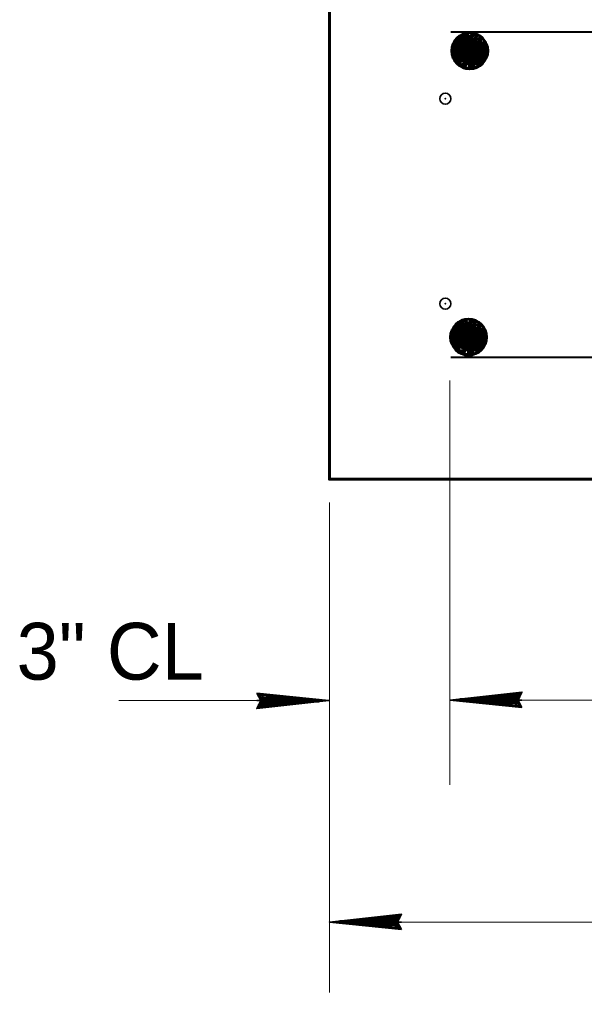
# Model space of a CAD drawing. Extents: x 4.49 to 7.69, y 0.28 to 2.27.
# Drawn here: x 5.7728 to 5.8557, y 1.3387 to 1.4815 of the extents above; entities that cross this region are included whole.
import ezdxf

# ---------------------------------------------------------------- set-up
doc = ezdxf.new("R2010")
doc.units = 0
doc.header["$LTSCALE"] = 0.0033
doc.header["$PDMODE"] = 32
doc.header["$PDSIZE"] = 0.00165
doc.layers.add('1', color=7, linetype='Continuous', lineweight=35)

msp = doc.modelspace()

# ---------------------------------------------------------------- linework, layer by layer
at = {"layer": '1', "lineweight": 40}
for p, q in [((5.836083, 1.479667), (6.217, 1.479667)), ((5.83675, 1.478417), (5.841333, 1.47625)), ((5.837, 1.478), (5.840917, 1.47725)), ((5.837083, 1.478417), (5.841, 1.47775)), ((5.837083, 1.47825), (5.841, 1.4775)), ((5.837167, 1.47875), (5.841, 1.478083)), ((5.839083, 1.477917), (5.840417, 1.478917)), ((5.841167, 1.478083), (5.839917, 1.47925)), ((5.83675, 1.476583), (5.840667, 1.475833)), ((5.836833, 1.477), (5.840667, 1.47625)), ((5.836833, 1.476833), (5.840667, 1.476083)), ((5.836917, 1.477417), (5.84075, 1.47675)), ((5.836917, 1.47725), (5.84075, 1.4765)), ((5.837, 1.477833), (5.840917, 1.477083)), ((5.837, 1.477583), (5.840833, 1.476833)), ((5.836583, 1.475667), (5.840417, 1.474917)), ((5.836583, 1.4755), (5.840417, 1.47475)), ((5.836667, 1.476167), (5.840583, 1.475417)), ((5.836667, 1.476), (5.8405, 1.47525)), ((5.836667, 1.47575), (5.8405, 1.475083)), ((5.840917, 1.47525), (5.837167, 1.474833)), ((5.837, 1.43675), (5.840833, 1.436083)), ((5.838917, 1.435917), (5.84025, 1.436917)), ((5.841, 1.436083), (5.83975, 1.43725)), ((5.836583, 1.436417), (5.841167, 1.43425)), ((5.83675, 1.435417), (5.840583, 1.43475)), ((5.83675, 1.43525), (5.840583, 1.4345)), ((5.836833, 1.436), (5.84075, 1.43525)), ((5.836833, 1.435833), (5.84075, 1.435083)), ((5.836833, 1.435583), (5.840667, 1.434833)), ((5.836917, 1.436417), (5.840833, 1.43575)), ((5.836917, 1.43625), (5.840833, 1.4355)), ((5.836417, 1.433667), (5.84025, 1.432917)), ((5.8365, 1.434167), (5.840417, 1.433417)), ((5.8365, 1.434), (5.840333, 1.43325)), ((5.8365, 1.43375), (5.840333, 1.433083)), ((5.836583, 1.434583), (5.8405, 1.433833)), ((5.836667, 1.435), (5.8405, 1.43425)), ((5.836667, 1.434833), (5.8405, 1.434083)), ((5.836417, 1.4335), (5.84025, 1.43275)), ((5.84075, 1.43325), (5.837, 1.432833)), ((5.836083, 1.431917), (6.216583, 1.431917))]:
    msp.add_line(p, q, dxfattribs=at)
at = {"layer": '1', "lineweight": 60}
for p, q in [((5.837, 1.478417), (5.836833, 1.4755)), ((5.83725, 1.478417), (5.837, 1.4755)), ((5.837417, 1.478417), (5.83725, 1.475417)), ((5.837583, 1.478417), (5.837333, 1.475417)), ((5.83775, 1.478417), (5.837583, 1.475417)), ((5.838, 1.478417), (5.837833, 1.475417)), ((5.83825, 1.478417), (5.838, 1.475417)), ((5.838333, 1.478333), (5.838167, 1.475417)), ((5.8385, 1.478333), (5.838333, 1.475417)), ((5.838667, 1.478333), (5.8385, 1.475417)), ((5.838917, 1.478333), (5.838667, 1.475417)), ((5.839083, 1.478333), (5.838917, 1.475417)), ((5.839333, 1.47825), (5.839083, 1.475333)), ((5.839583, 1.47825), (5.839333, 1.475333)), ((5.83975, 1.47825), (5.839583, 1.475333)), ((5.839833, 1.47825), (5.839667, 1.475333)), ((5.84, 1.47825), (5.839833, 1.475333)), ((5.840083, 1.47825), (5.839917, 1.475333)), ((5.840333, 1.478167), (5.840083, 1.47525)), ((5.8405, 1.478167), (5.840333, 1.47525)), ((5.840667, 1.478167), (5.840417, 1.47525)), ((5.840833, 1.478167), (5.840667, 1.47525)), ((5.841083, 1.478167), (5.840917, 1.47525)), ((5.841333, 1.47625), (5.841167, 1.478083)), ((5.841333, 1.47625), (5.836583, 1.4755)), ((5.836833, 1.436417), (5.836667, 1.4335)), ((5.837083, 1.436417), (5.836833, 1.4335)), ((5.83725, 1.436417), (5.837083, 1.433417)), ((5.837417, 1.436417), (5.837167, 1.433417)), ((5.837583, 1.436417), (5.837417, 1.433417)), ((5.837833, 1.436417), (5.837667, 1.433417)), ((5.838083, 1.436417), (5.837833, 1.433417)), ((5.838167, 1.436333), (5.838, 1.433417)), ((5.838333, 1.436333), (5.838167, 1.433417)), ((5.8385, 1.436333), (5.838333, 1.433417)), ((5.83875, 1.436333), (5.8385, 1.433417)), ((5.838917, 1.436333), (5.83875, 1.433417)), ((5.839167, 1.43625), (5.838917, 1.433333)), ((5.839417, 1.43625), (5.839167, 1.433333)), ((5.839583, 1.43625), (5.839417, 1.433333)), ((5.839667, 1.43625), (5.8395, 1.433333)), ((5.839833, 1.43625), (5.839667, 1.433333)), ((5.839917, 1.43625), (5.83975, 1.433333)), ((5.840167, 1.436167), (5.839917, 1.43325)), ((5.840333, 1.436167), (5.840167, 1.43325)), ((5.8405, 1.436167), (5.84025, 1.43325)), ((5.840667, 1.436167), (5.8405, 1.43325)), ((5.840917, 1.436167), (5.84075, 1.43325)), ((5.841167, 1.43425), (5.841, 1.436083)), ((5.841167, 1.43425), (5.836417, 1.4335))]:
    msp.add_line(p, q, dxfattribs=at)
at = {"layer": '1', "lineweight": 13}
for p, q in [((5.835917, 1.4285), (5.835917, 1.369167)), ((5.81825, 1.410583), (5.81825, 1.338667)), ((5.787333, 1.3815), (5.808167, 1.3815)), ((5.835917, 1.381583), (6.216917, 1.381583)), ((5.81825, 1.349), (6.234583, 1.349))]:
    msp.add_line(p, q, dxfattribs=at)
at = {"layer": '1'}
for p, q in [((5.807833, 1.3825), (5.815667, 1.381583)), ((5.807833, 1.3825), (5.815667, 1.381583)), ((5.807833, 1.382417), (5.815667, 1.381583)), ((5.807833, 1.382333), (5.815667, 1.3815)), ((5.807833, 1.382333), (5.815667, 1.381333)), ((5.84625, 1.382667), (5.838917, 1.381833)), ((5.84625, 1.3825), (5.838917, 1.38175)), ((5.84625, 1.382417), (5.838917, 1.381583)), ((5.846333, 1.38225), (5.839, 1.3815)), ((5.807583, 1.3815), (5.818167, 1.3815)), ((5.80775, 1.380833), (5.815083, 1.381583)), ((5.807833, 1.380667), (5.815167, 1.3815)), ((5.807833, 1.380583), (5.815167, 1.381333)), ((5.807833, 1.380417), (5.815167, 1.38125)), ((5.8465, 1.381583), (5.835917, 1.381583)), ((5.84625, 1.38075), (5.838417, 1.38175)), ((5.84625, 1.38075), (5.838417, 1.381583)), ((5.84625, 1.380583), (5.838417, 1.3815)), ((5.84625, 1.380583), (5.838417, 1.3815)), ((5.84625, 1.380667), (5.838417, 1.3815)), ((5.828583, 1.350083), (5.82125, 1.34925)), ((5.828583, 1.349917), (5.82125, 1.349167)), ((5.828583, 1.349833), (5.82125, 1.349)), ((5.828667, 1.349667), (5.821333, 1.348917)), ((5.828833, 1.349), (5.81825, 1.349)), ((5.828583, 1.348167), (5.82075, 1.349167)), ((5.828583, 1.348167), (5.82075, 1.349)), ((5.828583, 1.348), (5.82075, 1.348917)), ((5.828583, 1.348), (5.82075, 1.348917)), ((5.828583, 1.348083), (5.82075, 1.348917))]:
    msp.add_line(p, q, dxfattribs=at)
at = {"layer": '1', "lineweight": 60}
for points in [[(5.81825, 1.497333), (5.81825, 1.414), (6.234917, 1.414), (6.234917, 1.497333)], [(5.840417, 1.47475), (5.840417, 1.478917), (5.83875, 1.47425), (5.83925, 1.479417), (5.837167, 1.474833), (5.837917, 1.479333), (5.8395, 1.474333), (5.836333, 1.477667), (5.841167, 1.478083), (5.837917, 1.474417), (5.839917, 1.47925), (5.83675, 1.478417), (5.836583, 1.4755)], [(5.837167, 1.474833), (5.838667, 1.477083), (5.8365, 1.478), (5.8385, 1.479417), (5.838667, 1.477167), (5.840333, 1.474833), (5.836333, 1.477167), (5.839083, 1.477917)], [(5.836167, 1.47675), (5.841333, 1.477417), (5.83675, 1.478417)], [(5.839917, 1.47925), (5.838667, 1.477083), (5.840917, 1.47525)], [(5.84025, 1.43275), (5.84025, 1.436917), (5.838583, 1.43225), (5.839083, 1.437417), (5.837, 1.432833), (5.83775, 1.437333), (5.839333, 1.432333), (5.836167, 1.435667), (5.841, 1.436083), (5.83775, 1.432417), (5.83975, 1.43725), (5.836583, 1.436417), (5.836417, 1.4335)], [(5.837, 1.432833), (5.8385, 1.435083), (5.836333, 1.436), (5.838333, 1.437417), (5.8385, 1.435167), (5.840167, 1.432833), (5.836167, 1.435167), (5.838917, 1.435917)], [(5.83975, 1.43725), (5.8385, 1.435083), (5.84075, 1.43325)], [(5.836, 1.43475), (5.841167, 1.435417), (5.836583, 1.436417)]]:
    msp.add_lwpolyline(points, dxfattribs=at)
at = {"layer": '1', "lineweight": 40}
for points in [[(5.836583, 1.4755), (5.838667, 1.47425), (5.840417, 1.47475), (5.841333, 1.47625)], [(5.836417, 1.4335), (5.8385, 1.43225), (5.84025, 1.43275), (5.841167, 1.43425)]]:
    msp.add_lwpolyline(points, dxfattribs=at)
at = {"layer": '1'}
for points in [[(5.807583, 1.382583), (5.818167, 1.3815), (5.807583, 1.380333), (5.808167, 1.3815)], [(5.8465, 1.3805), (5.835917, 1.381583), (5.8465, 1.38275), (5.845917, 1.381583)], [(5.808333, 1.381583), (5.813, 1.381667), (5.813, 1.381583), (5.812083, 1.381583), (5.808333, 1.381667), (5.811333, 1.38175), (5.808167, 1.381833), (5.810417, 1.381917), (5.808167, 1.382), (5.811667, 1.38175), (5.816333, 1.381583), (5.815417, 1.381333), (5.816667, 1.381333), (5.808333, 1.381333), (5.81075, 1.381167), (5.808167, 1.381167), (5.8135, 1.381583), (5.808167, 1.380917)], [(5.84575, 1.3815), (5.841083, 1.381417), (5.841083, 1.3815), (5.842, 1.3815), (5.84575, 1.381417), (5.84275, 1.381333), (5.845917, 1.38125), (5.843667, 1.381167), (5.845917, 1.381083), (5.842417, 1.381333), (5.83775, 1.3815), (5.838667, 1.38175), (5.837417, 1.38175), (5.84575, 1.38175), (5.843333, 1.381917), (5.845917, 1.381917), (5.840583, 1.3815), (5.845917, 1.382167)], [(5.828833, 1.347917), (5.81825, 1.349), (5.828833, 1.350167), (5.82825, 1.349)], [(5.828083, 1.348917), (5.823417, 1.348833), (5.823417, 1.348917), (5.824333, 1.348917), (5.828083, 1.348833), (5.825083, 1.34875), (5.82825, 1.348667), (5.826, 1.348583), (5.82825, 1.3485), (5.82475, 1.34875), (5.820083, 1.348917), (5.821, 1.349167), (5.81975, 1.349167), (5.828083, 1.349167), (5.825667, 1.349333), (5.82825, 1.349333), (5.822917, 1.348917), (5.82825, 1.349583)]]:
    msp.add_lwpolyline(points, close=True, dxfattribs=at)
for points in [[(5.808333, 1.381583), (5.807917, 1.382333), (5.808167, 1.382083), (5.808333, 1.38175), (5.808583, 1.381833), (5.808417, 1.382167), (5.80825, 1.381417), (5.808083, 1.380917), (5.807833, 1.3805)], [(5.84575, 1.3815), (5.846167, 1.38075), (5.845917, 1.381), (5.84575, 1.381333), (5.8455, 1.38125), (5.845667, 1.380917), (5.845833, 1.381667), (5.846, 1.382167), (5.84625, 1.382583)], [(5.828083, 1.348917), (5.8285, 1.348167), (5.82825, 1.348417), (5.828083, 1.34875), (5.827833, 1.348667), (5.828, 1.348333), (5.828167, 1.349083), (5.828333, 1.349583), (5.828583, 1.35)]]:
    msp.add_lwpolyline(points, dxfattribs=at)
at = {"layer": '1', "lineweight": 60}
for centre in [(5.838833, 1.47685), (5.838667, 1.43485)]:
    msp.add_circle(centre, 0.00264, dxfattribs=at)
at = {"layer": '1'}
for p in [(5.83825, 1.475), (5.83525, 1.469833), (5.83525, 1.43975), (5.83825, 1.435167)]:
    msp.add_point(p, dxfattribs=at)

# ---------------------------------------------------------------- texts
msp.add_text('3" CL', height=0.008334, dxfattribs=at).set_placement((5.772333, 1.384583))

doc.saveas('drawing.dxf')
